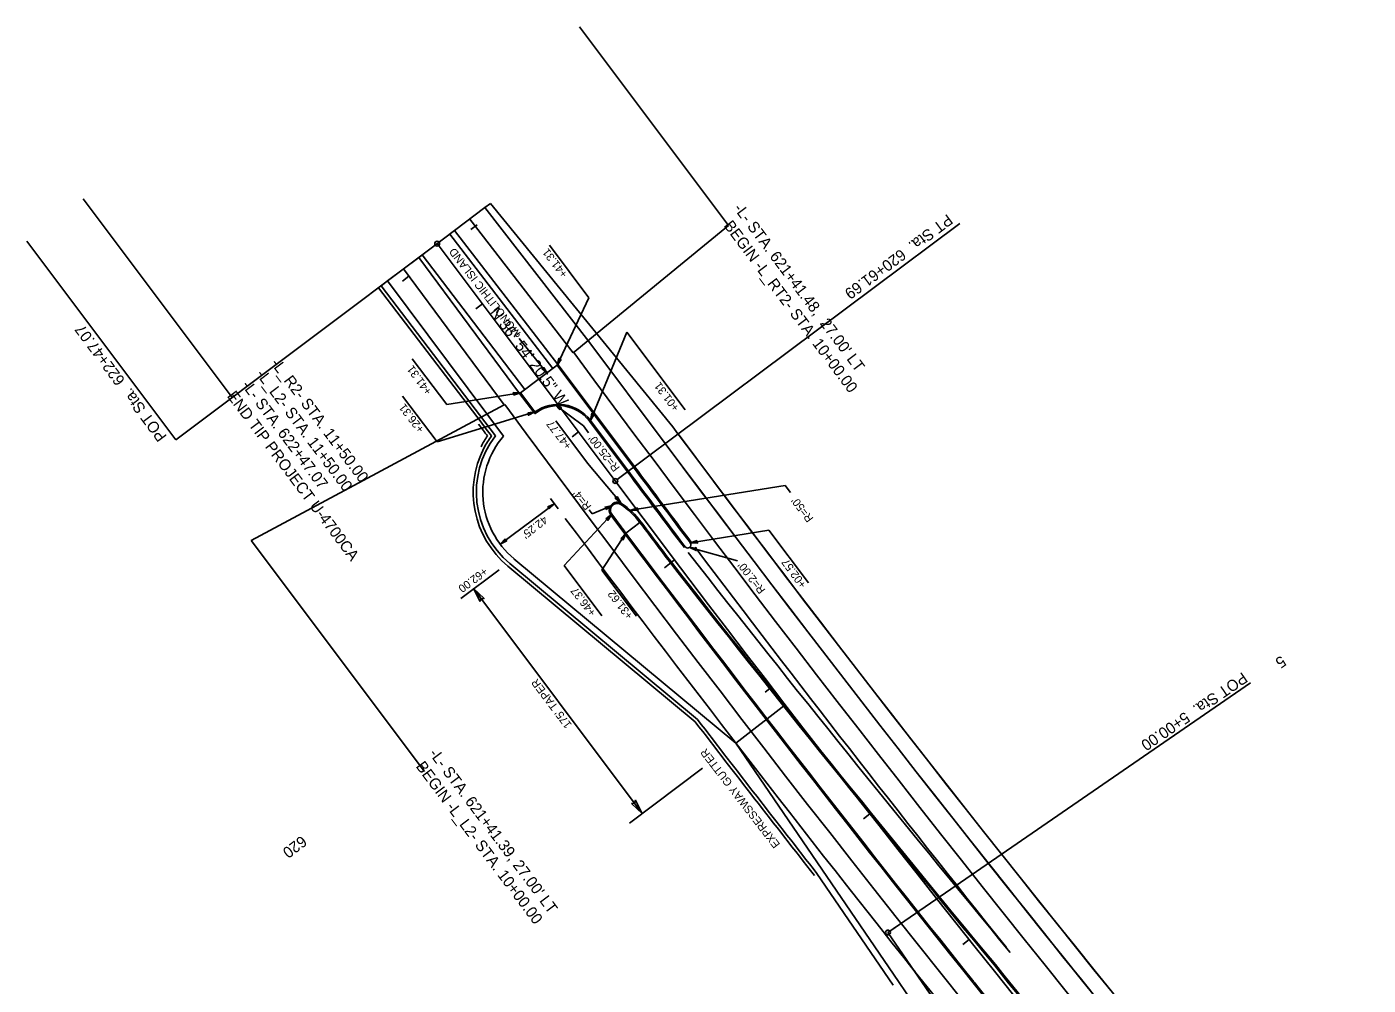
# Model space of a CAD drawing. Extents: x 1262642 to 1268358, y 767825 to 773481.
# Drawn here: x 1265547 to 1266385, y 772883 to 773481 of the extents above; entities that cross this region are included whole.
import ezdxf

# ---------------------------------------------------------------- set-up
doc = ezdxf.new("R2010")
doc.units = 0
for name, color, linetype in [('Default', 7, 'Continuous'), ('Prop Conc 1ft 6in Curb and Gutter', 7, 'Continuous'), ('Prop Conc 5in Monolithic Keyed In Island', 7, 'Continuous'), ('Prop Conc Expressway Gutter', 7, 'Continuous'), ('Prop Dimension', 7, 'Continuous'), ('Prop Dimension Text', 7, 'Continuous'), ('Prop EOT', 7, 'Continuous'), ('Prop Horizontal Alignment', 7, 'Continuous'), ('Prop Horizontal Alignment Direction Label', 7, 'Continuous'), ('Prop Horizontal Alignment Station Label', 7, 'Continuous'), ('Prop Horizontal Alignment Tick Label', 7, 'Continuous'), ('Prop Horizontal Alignment Tick Large', 7, 'Continuous'), ('Prop Horizontal Alignment Tick Small', 7, 'Continuous'), ('Prop Lane Lines', 7, 'Continuous'), ('Prop North Arrow for Plan Sheets CELL', 7, 'Continuous'), ('Prop Paved Shoulder', 7, 'Continuous'), ('Prop Shade Light', 7, 'Continuous'), ('Prop Shade Medium', 7, 'Continuous'), ('Prop Terminator CELL', 7, 'Continuous')]:
    doc.layers.add(name, color=color, linetype=linetype)

msp = doc.modelspace()

# ---------------------------------------------------------------- linework, layer by layer
at = {"layer": 'Default'}
for p, q in [((1265843, 773158.28), (1265876.88, 773183.54)), ((1265874.47, 773186.74), (1265879.28, 773180.34))]:
    msp.add_line(p, q, dxfattribs=at)
for centre, radius, start, end in [((1318019.14, 812417.98), 65262.56, 216.8998653, 216.9078994), ((1318021.62, 812418.01), 65262.56, 216.8985738, 216.9078994), ((1265886.32, 773190.62), 62.17, 145.51647, 152.69456), ((1265886.18, 773190.71), 60, 144.13462, 152.69294)]:
    msp.add_arc(centre, radius, start, end, dxfattribs=at)
at = {"layer": 'Prop Conc 1ft 6in Curb and Gutter'}
for centre, radius, start, end in [((1275047.31, 780021.23), 11414.25, 216.917495, 218.698035), ((1275047.31, 780021.23), 11397.75, 218.697492, 219.840867), ((1275045.61, 780019.75), 11412, 218.698035, 219.543975)]:
    msp.add_arc(centre, radius, start, end, dxfattribs=at)
at = {"layer": 'Prop Conc 5in Monolithic Keyed In Island'}
for p, q in [((1265855.76, 773252.82), (1265878.55, 773269.94)), ((1265926.38, 773206.25), (1265878.55, 773269.94)), ((1265864.77, 773240.83), (1265855.76, 773252.82)), ((1265923.17, 773203.85), (1265899.37, 773235.55)), ((1265921.6, 773165.09), (1265912.74, 773176.9)), ((1265930.39, 773171.7), (1265921.6, 773165.09))]:
    msp.add_line(p, q, dxfattribs=at)
for centre, radius, start, end in [((1265879.38, 773220.54), 25, 36.9057, 125.75971), ((1275047.31, 780021.23), 11385.75, 216.766365, 217.063527), ((1275047.31, 780021.23), 11389.75, 216.766365, 217.063527), ((1265916.14, 773179.45), 4.25, 56.0686, 216.84336), ((1265891.02, 773142.12), 49.25, 36.91749, 56.0686), ((1275047.31, 780021.23), 11414.25, 216.843363, 216.917495), ((1275047.31, 780021.23), 11403.25, 216.917495, 217.064069), ((1265960.25, 773157.83), 2, 217.06353, 37.06353), ((1274926.3, 780171.46), 11398.87, 218.033261, 219.667152)]:
    msp.add_arc(centre, radius, start, end, dxfattribs=at)
at = {"layer": 'Prop Conc Expressway Gutter'}
for p, q in [((1265831.17, 773234.35), (1265767.02, 773318.42)), ((1265964.94, 773047.28), (1265847.84, 773144.55))]:
    msp.add_line(p, q, dxfattribs=at)
for centre, radius, start, end in [((1265886.18, 773190.71), 60, 152.69294, 230.28388), ((1275047.31, 780021.23), 11451, 217.519045, 218.126365)]:
    msp.add_arc(centre, radius, start, end, dxfattribs=at)
at = {"layer": 'Prop Dimension'}
for p, q in [((1265873.86, 773344.95), (1265898.51, 773312.12)), ((1265878.55, 773269.94), (1265898.51, 773312.12)), ((1265899.37, 773235.55), (1265922.22, 773290.65)), ((1265958.63, 773242.17), (1265922.22, 773290.65)), ((1265872.57, 773264.62), (1265854.88, 773286.69)), ((1265788.13, 773274.1), (1265809.68, 773245.41)), ((1265803.59, 773222.09), (1265782.05, 773250.78)), ((1265855.76, 773252.82), (1265809.68, 773245.41)), ((1265864.77, 773240.83), (1265803.59, 773222.09)), ((1265877.24, 773245.45), (1265895.05, 773232.13)), ((1265877.84, 773235.25), (1265897.61, 773208.93)), ((1265895.08, 773232.08), (1265898.27, 773227.83)), ((1265918.35, 773184.06), (1265897.61, 773208.93)), ((1265924.64, 773179.41), (1266021.11, 773194.93)), ((1266024.37, 773190.58), (1266021.11, 773194.93)), ((1265913.06, 773182.38), (1265900.59, 773177.3)), ((1265912.74, 773176.9), (1265882.96, 773144.9)), ((1265898.74, 773179.76), (1265900.59, 773177.3)), ((1265921.6, 773165.09), (1265906.63, 773142.06)), ((1265961.85, 773159.03), (1266010.98, 773166.94)), ((1266035.63, 773134.11), (1266010.98, 773166.94)), ((1265961.45, 773156.23), (1265991.27, 773147.91)), ((1265906.59, 773113.44), (1265882.96, 773144.9)), ((1265928.17, 773113.38), (1265906.63, 773142.06))]:
    msp.add_line(p, q, dxfattribs=at)
at = {"layer": 'Prop Dimension Text'}
for p, q in [((1265842.41, 773142.22), (1265818.5, 773124.26)), ((1265931.76, 772990.09), (1265826.49, 773130.26)), ((1265923.77, 772984.08), (1265969.35, 773018.31))]:
    msp.add_line(p, q, dxfattribs=at)
for points in [[(1265830.44, 773122.38), (1265826.28, 773130.5), (1265832.99, 773124.23), (1265831.02, 773124.19)], [(1265925.12, 772996.35), (1265931.76, 772990.09), (1265927.61, 772998.28), (1265927.02, 772996.4)]]:
    msp.add_lwpolyline(points, close=True, dxfattribs=at)
at = {"layer": 'Prop EOT'}
for p, q in [((1265814.51, 773354.1), (1265833.53, 773368.42)), ((1265833.53, 773368.42), (1265836.93, 773370.94)), ((1265898.34, 773284.8), (1265833.53, 773368.42)), ((1265792.17, 773337.33), (1265814.51, 773354.1)), ((1265879.15, 773270.39), (1265814.51, 773354.1)), ((1265772.63, 773322.65), (1265792.17, 773337.33)), ((1265855.16, 773252.37), (1265792.17, 773337.33)), ((1265768.61, 773319.63), (1265772.63, 773322.65)), ((1265835.97, 773237.96), (1265772.63, 773322.65)), ((1265946.15, 773221.14), (1265898.34, 773284.8)), ((1265926.96, 773206.72), (1265879.15, 773270.39)), ((1265864.61, 773239.78), (1265855.16, 773252.37)), ((1265864.61, 773239.78), (1265864.81, 773239.93)), ((1265845.12, 773225.78), (1265835.97, 773237.96)), ((1265922.56, 773203.42), (1265898.77, 773235.1)), ((1265990.28, 773034.03), (1265851.67, 773149.17)), ((1265990.28, 773034.03), (1266091.84, 772885.1)), ((1266091.84, 772885.1), (1266156.33, 772791.33))]:
    msp.add_line(p, q, dxfattribs=at)
for centre, radius, start, end in [((1265879.38, 773220.54), 24.25, 36.9057, 126.9057), ((1265886.18, 773190.71), 58, 142.5881, 230.28388), ((1265886.18, 773190.71), 54, 139.49665, 230.28388), ((1275047.31, 780021.23), 11361, 216.766365, 222.716029), ((1275047.31, 780021.23), 11385, 216.766365, 217.063527), ((1275047.31, 780021.23), 11390.5, 216.766365, 217.063919), ((1265916.14, 773179.45), 5, 56.0686, 216.84336), ((1265891.02, 773142.12), 50, 36.91749, 56.0686), ((1275047.31, 780021.23), 11415, 216.843363, 218.698216), ((1275047.31, 780021.23), 11402.5, 216.917495, 217.064037), ((1274926.3, 780171.46), 11398.12, 218.033293, 219.667184), ((1275047.31, 780021.23), 11397, 218.69746, 219.840704), ((1275045.61, 780019.75), 11412.75, 218.698035, 219.544138)]:
    msp.add_arc(centre, radius, start, end, dxfattribs=at)
at = {"layer": 'Prop Horizontal Alignment'}
for p, q in [((1265888.64, 773277.72), (1265824.11, 773361.31)), ((1265914.96, 773197.72), (1265803.65, 773345.94)), ((1265845.52, 773245.23), (1265782.58, 773330.12)), ((1266085.32, 772915.75), (1266166.21, 772798.14)), ((1266085.32, 772915.75), (1266166.21, 772798.14)), ((1266101.72, 772891.9), (1266166.21, 772798.14))]:
    msp.add_line(p, q, dxfattribs=at)
msp.add_arc((1275047.31, 780021.23), 11400, 216.766365, 222.993587, dxfattribs=at)
at = {"layer": 'Prop Horizontal Alignment Station Label'}
for p, q in [((1265985.75, 773357.3), (1265892.6, 773481.34)), ((1265675.68, 773249.84), (1265582.53, 773373.89)), ((1265916.16, 773198.61), (1266130.19, 773358.53)), ((1265985.75, 773357.3), (1265945.37, 773324.21)), ((1265640.43, 773223.37), (1265547.28, 773347.41)), ((1265802.45, 773345.04), (1265640.43, 773223.37)), ((1265945.37, 773324.21), (1265888.64, 773277.72)), ((1265757.38, 773198.06), (1265845.52, 773245.23)), ((1265687.41, 773160.62), (1265757.38, 773198.06)), ((1265795.78, 773016.31), (1265687.41, 773160.62)), ((1266086.56, 772916.6), (1266311.9, 773071.59))]:
    msp.add_line(p, q, dxfattribs=at)
for centre in [(1265803.65, 773345.94), (1265914.96, 773197.72), (1266085.32, 772915.75)]:
    msp.add_circle(centre, 1.5, dxfattribs=at)
at = {"layer": 'Prop Horizontal Alignment Tick Large'}
for p, q in [((1265952.02, 773148.39), (1265945.64, 773143.57)), ((1266085.32, 772915.75), (1266091.91, 772920.28))]:
    msp.add_line(p, q, dxfattribs=at)
at = {"layer": 'Prop Horizontal Alignment Tick Small'}
for p, q in [((1265828.59, 773357.68), (1265824.6, 773354.68)), ((1265785.96, 773325.56), (1265781.96, 773322.56)), ((1265831.91, 773308.31), (1265827.91, 773305.31)), ((1265891.96, 773228.35), (1265887.96, 773225.34)), ((1266012.66, 773068.88), (1266008.7, 773065.83)), ((1266073.99, 772989.89), (1266070.06, 772986.81)), ((1266136.01, 772911.45), (1266132.11, 772908.33))]:
    msp.add_line(p, q, dxfattribs=at)
at = {"layer": 'Prop Lane Lines'}
for p, q in [((1265888.64, 773277.72), (1265824.11, 773361.31)), ((1265845.52, 773245.23), (1265782.58, 773330.12))]:
    msp.add_line(p, q, dxfattribs=at)
for centre, radius, start, end in [((1275047.31, 780021.23), 11373, 216.364944, 223.132748), ((1275047.31, 780021.23), 11427, 216.367499, 223.547684), ((1275047.31, 780021.23), 11439, 216.766365, 220.467863), ((1275047.31, 780021.23), 11385, 217.083418, 218.677882), ((1274926.3, 780171.46), 11386.12, 218.054168, 219.667695)]:
    msp.add_arc(centre, radius, start, end, dxfattribs=at)
at = {"layer": 'Prop North Arrow for Plan Sheets CELL'}
msp.add_line((1265990.28, 773034.03), (1266021.16, 773057.85), dxfattribs=at)
at = {"layer": 'Prop Paved Shoulder'}
for p, q in [((1265950.92, 773231.44), (1265836.93, 773370.94)), ((1265875.95, 773267.99), (1265811.53, 773351.87)), ((1265858.36, 773254.78), (1265794.34, 773338.96)), ((1265840.11, 773225.94), (1265768.61, 773319.63)), ((1265954.14, 773227.14), (1265950.92, 773231.44)), ((1265966.39, 773048.67), (1265849.11, 773146.09)), ((1266040.94, 772952.64), (1266088.53, 772882.85))]:
    msp.add_line(p, q, dxfattribs=at)
for radius, start, end in [(11351, 216.766365, 222.716029), (11449, 217.517926, 218.126365)]:
    msp.add_arc((1275047.31, 780021.23), radius, start, end, dxfattribs=at)
at = {"layer": 'Prop Shade Light'}
for p, q in [((1265833.53, 773368.42), (1265836.93, 773370.94)), ((1265898.34, 773284.8), (1265833.53, 773368.42)), ((1265836.93, 773370.94), (1265950.92, 773231.44)), ((1265772.63, 773322.65), (1265768.61, 773319.63)), ((1265835.97, 773237.96), (1265772.63, 773322.65)), ((1265768.61, 773319.63), (1265840.11, 773225.94)), ((1265946.15, 773221.14), (1265898.34, 773284.8)), ((1265845.12, 773225.78), (1265835.97, 773237.96)), ((1265950.92, 773231.44), (1265954.14, 773227.14)), ((1265990.28, 773034.03), (1265851.67, 773149.17)), ((1265849.11, 773146.09), (1265966.39, 773048.67)), ((1266091.84, 772885.1), (1265990.28, 773034.03)), ((1266040.94, 772952.64), (1266088.54, 772882.83)), ((1266156.33, 772791.33), (1266091.84, 772885.1))]:
    msp.add_line(p, q, dxfattribs=at)
for centre, radius, start, end in [((1265886.18, 773190.71), 58, 142.5881, 230.28388), ((1265886.18, 773190.71), 54, 139.49665, 230.28388), ((1275047.31, 780021.23), 11351, 216.765763, 222.716029), ((1275047.31, 780021.23), 11361, 216.765886, 222.716029), ((1275047.31, 780021.23), 11449, 217.517926, 218.126365)]:
    msp.add_arc(centre, radius, start, end, dxfattribs=at)
at = {"layer": 'Prop Shade Medium'}
for p, q in [((1265878.55, 773269.94), (1265855.76, 773252.82)), ((1265926.38, 773206.25), (1265878.55, 773269.94)), ((1265855.76, 773252.82), (1265864.77, 773240.83)), ((1265899.37, 773235.55), (1265923.17, 773203.85)), ((1265921.6, 773165.09), (1265912.74, 773176.9)), ((1265930.39, 773171.7), (1265921.6, 773165.09))]:
    msp.add_line(p, q, dxfattribs=at)
for centre, radius, start, end in [((1265879.38, 773220.54), 25, 36.9057, 125.75971), ((1275047.31, 780021.23), 11385.75, 216.766365, 217.063527), ((1275047.31, 780021.23), 11389.75, 216.766365, 217.063527), ((1265916.14, 773179.45), 4.25, 56.0686, 216.84336), ((1265891.02, 773142.12), 49.25, 36.91749, 56.0686), ((1265960.25, 773157.83), 2, 217.06353, 37.06353)]:
    msp.add_arc(centre, radius, start, end, dxfattribs=at)
at = {"layer": 'Prop Terminator CELL'}
for points in [[(1265881.17, 773273.67), (1265878.55, 773269.94), (1265879.76, 773274.37), (1265880.24, 773273.51)], [(1265870.36, 773268.61), (1265872.57, 773264.62), (1265869.11, 773267.65), (1265870.1, 773267.7)], [(1265851.44, 773251.34), (1265855.76, 773252.82), (1265851.16, 773252.89), (1265851.86, 773252.2)], [(1265860.24, 773240.25), (1265864.77, 773240.83), (1265860.67, 773238.74), (1265860.99, 773239.67)], [(1265880.38, 773242.13), (1265877.24, 773245.45), (1265881.34, 773243.38), (1265880.4, 773243.08)], [(1265900.38, 773240), (1265899.37, 773235.55), (1265901.84, 773239.42), (1265900.88, 773239.2)], [(1265873.73, 773180.23), (1265876.88, 773183.54), (1265872.77, 773181.48), (1265873.71, 773181.18)], [(1265909.18, 773179.97), (1265913.06, 773182.38), (1265908.56, 773181.42), (1265909.4, 773180.89)], [(1265916.05, 773188), (1265918.35, 773184.06), (1265914.83, 773187.01), (1265915.81, 773187.08)], [(1265928.96, 773180.89), (1265924.64, 773179.41), (1265929.24, 773179.34), (1265928.54, 773180.04)], [(1265909.1, 773174.14), (1265912.74, 773176.9), (1265910.24, 773173.05), (1265910.05, 773174.01)], [(1265918.5, 773161.74), (1265921.6, 773165.09), (1265919.8, 773160.86), (1265919.45, 773161.78)], [(1265846.14, 773161.59), (1265843, 773158.28), (1265847.1, 773160.34), (1265846.16, 773160.64)], [(1265965.99, 773155.77), (1265961.45, 773156.23), (1265965.59, 773154.24), (1265965.25, 773155.17)], [(1265966.17, 773160.51), (1265961.85, 773159.03), (1265966.44, 773158.96), (1265965.75, 773159.66)]]:
    msp.add_lwpolyline(points, close=True, dxfattribs=at)

# ---------------------------------------------------------------- texts
at = {"layer": 'Prop Dimension Text'}
for s, rotation, p in [('MONOLITHIC ISLAND', 127.64384, (1265856.14, 773290.01)), ('+41.31', 127.64384, (1265885.56, 773327.1)), ('+41.31', 126.16755, (1265800.64, 773253.75)), ('+01.31', 127.0765, (1265955.3, 773243.54)), ('+26.31', 127.64384, (1265795.93, 773230.16)), ('+47.77', 127.64384, (1265888.1, 773219.76)), ("R=25.00'", 127.64384, (1265918.04, 773205.99)), ("R=4'", 127.64384, (1265900.32, 773181.94)), ("R=50'", 127.15506, (1266039.02, 773174.33)), ("42.25'", 217.64384, (1265870.27, 773176.22)), ('+02.57', 126.16755, (1266034.68, 773133.06)), ('+62.00', 216.9057, (1265832.87, 773144.01)), ("R=2.00'", 127.64384, (1266009.06, 773129.69)), ('+46.37', 127.64384, (1265903.23, 773115.65)), ('+31.62', 127.64384, (1265926.36, 773113.68)), ("175' TAPER", 126.9057, (1265888.03, 773045.48)), ('EXPRESSWAY GUTTER', 127.64384, (1266018.17, 772970.83))]:
    msp.add_text(s, height=5, rotation=rotation, dxfattribs=at).set_placement(p)
at = {"layer": 'Prop Horizontal Alignment Direction Label'}
for s, p in [("-L- STA. 621+41.48,  27.00' LT", (1265988.57, 773367.9)), ('BEGIN -L_RT2- STA. 10+00.00', (1265982.42, 773357.15)), ('N 36%%d 54\' 20.5" W', (1265836.23, 773302.88)), ('-L_R2- STA. 11+50.00', (1265699.34, 773271.17)), ('-L_L2- STA. 11+50.00', (1265690.24, 773264.34)), ('-L- STA. 622+47.07', (1265681.15, 773257.51)), ('END TIP PROJECT U-4700CA', (1265672.05, 773250.68)), ('BEGIN -L_L2- STA. 10+00.00', (1265790.01, 773019.43)), ("-L- STA. 621+41.39, 27.00' LT", (1265798.2, 773027.45))]:
    msp.add_text(s, height=7, rotation=306.9057, dxfattribs=at).set_placement(p)
at = {"layer": 'Prop Horizontal Alignment Station Label'}
for s, rotation, p in [('PT Sta.  620+61.69', 216.76636, (1266122.44, 773364.76)), ('POT Sta.  622+47.07', 126.67859, (1265635.07, 773225.58)), ('POT Sta.  5+00.00', 214.51931, (1266306.84, 773078.61))]:
    msp.add_text(s, height=7, rotation=rotation, dxfattribs=at).set_placement(p)
at = {"layer": 'Prop Horizontal Alignment Tick Label'}
for s, rotation, p in [('5', 214.51931, (1266330.98, 773088.96)), ('620', 217.07643, (1265718.89, 772976.61))]:
    msp.add_text(s, height=7, rotation=rotation, dxfattribs=at).set_placement(p)

doc.saveas('drawing.dxf')
